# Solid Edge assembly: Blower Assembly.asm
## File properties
Author: CADCIM
Template: NORMENG.ASM
Last saved by: Cadcim
Revision: 9
Application: Solid Edge
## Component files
Lower Housing.par
upper housing.par
Blower.par
cover.par
motorshaft.par
Motor.par
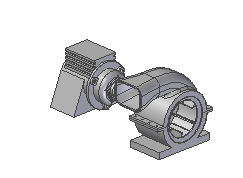
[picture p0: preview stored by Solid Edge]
